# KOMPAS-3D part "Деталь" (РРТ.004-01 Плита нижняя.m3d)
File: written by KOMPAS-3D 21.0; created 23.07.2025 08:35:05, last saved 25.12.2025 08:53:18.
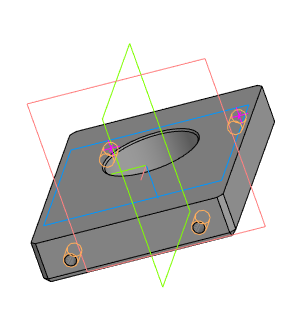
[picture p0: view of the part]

Document properties: Автор: User; Полное имя файла: C:\Users\User\Desktop\Ручной ротатор КД\Модели КД\РРТ.004-01 Плита нижняя.m3d

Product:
- Part/product: Деталь
    Масса: 0.321259

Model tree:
1. Эскиз:1
2. Элемент выдавливания:1
     Расстояние 1 = 12
3. Эскиз:2  (with: Элемент выдавливания:1)
4. Отверстие:1  (with: Элемент выдавливания:1)  (labels: M4)
     Глубина выреза = 10; Диаметр отверстия = 3.24223; Угол конуса дна = 118; Расстояние 1 = 7; Расстояние 2 = 45; Диаметр зенковки = 5; Глубина зенковки = 0.878886; Угол зенковки = 90
5. M4  (labels: M4; cil0_24705-2004 coarse)
     Длина резьбы = 8; Шаг резьбы = 0.7; Номинальный диаметр резьбы = 4
6. Отверстие:2  (with: Элемент выдавливания:1, M4)  (labels: M4; cil0_24705-2004 coarse)
     Глубина выреза = 10; Диаметр отверстия = 3.24223; Угол конуса дна = 118; Расстояние 1 = 7; Расстояние 2 = 9; Диаметр зенковки = 5; Глубина зенковки = 0.878886; Угол зенковки = 90; Длина резьбы = 8; Шаг резьбы = 0.7; Номинальный диаметр резьбы = 4
7. Зеркальный массив:1
8. Экземпляр ( 1 )
9. Экземпляр ( 2 )  (with: Отверстие:1)
10. Отверстие:2
11. Фаска:1  (with: Элемент выдавливания:1)
     Угол = 45; Длина 1 = 0.5; Длина 2 = 0.5
12. Фаска:2  (with: Элемент выдавливания:1)
     Угол = 45; Длина 1 = 1.5; Длина 2 = 1.5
